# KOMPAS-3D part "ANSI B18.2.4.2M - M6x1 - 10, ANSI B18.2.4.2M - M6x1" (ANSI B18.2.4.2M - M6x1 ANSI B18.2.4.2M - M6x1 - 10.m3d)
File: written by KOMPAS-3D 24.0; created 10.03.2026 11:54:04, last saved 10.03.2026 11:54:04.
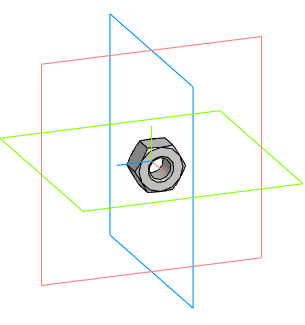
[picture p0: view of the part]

Document properties: Автор: R2D2; Полное имя файла: E:\Работа\Зайцев\BV3232P(4pc)-FP-3WL-F-ISO-H Кран шаровой DN.ru Ду15-100 Ру16\DN20\исходные материалы\ANSI B18.2.4.2M - M6x1 ANSI B18.2.4.2M - M6x1 - 10.m3d

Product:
- Body: Solid1  | qty 1
- Part/product: ANSI B18.2.4.2M - M6x1 - 10  | designation ANSI B18.2.4.2M - M6x1
    Комментарий: Типы метрических   шестигранных гаек   2
    additional columns: Сталь, мягкая

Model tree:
1. Solid1  (labels: Solid1)

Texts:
  ANSI B18.2.4.2M - M6x1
